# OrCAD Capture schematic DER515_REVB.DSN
size B
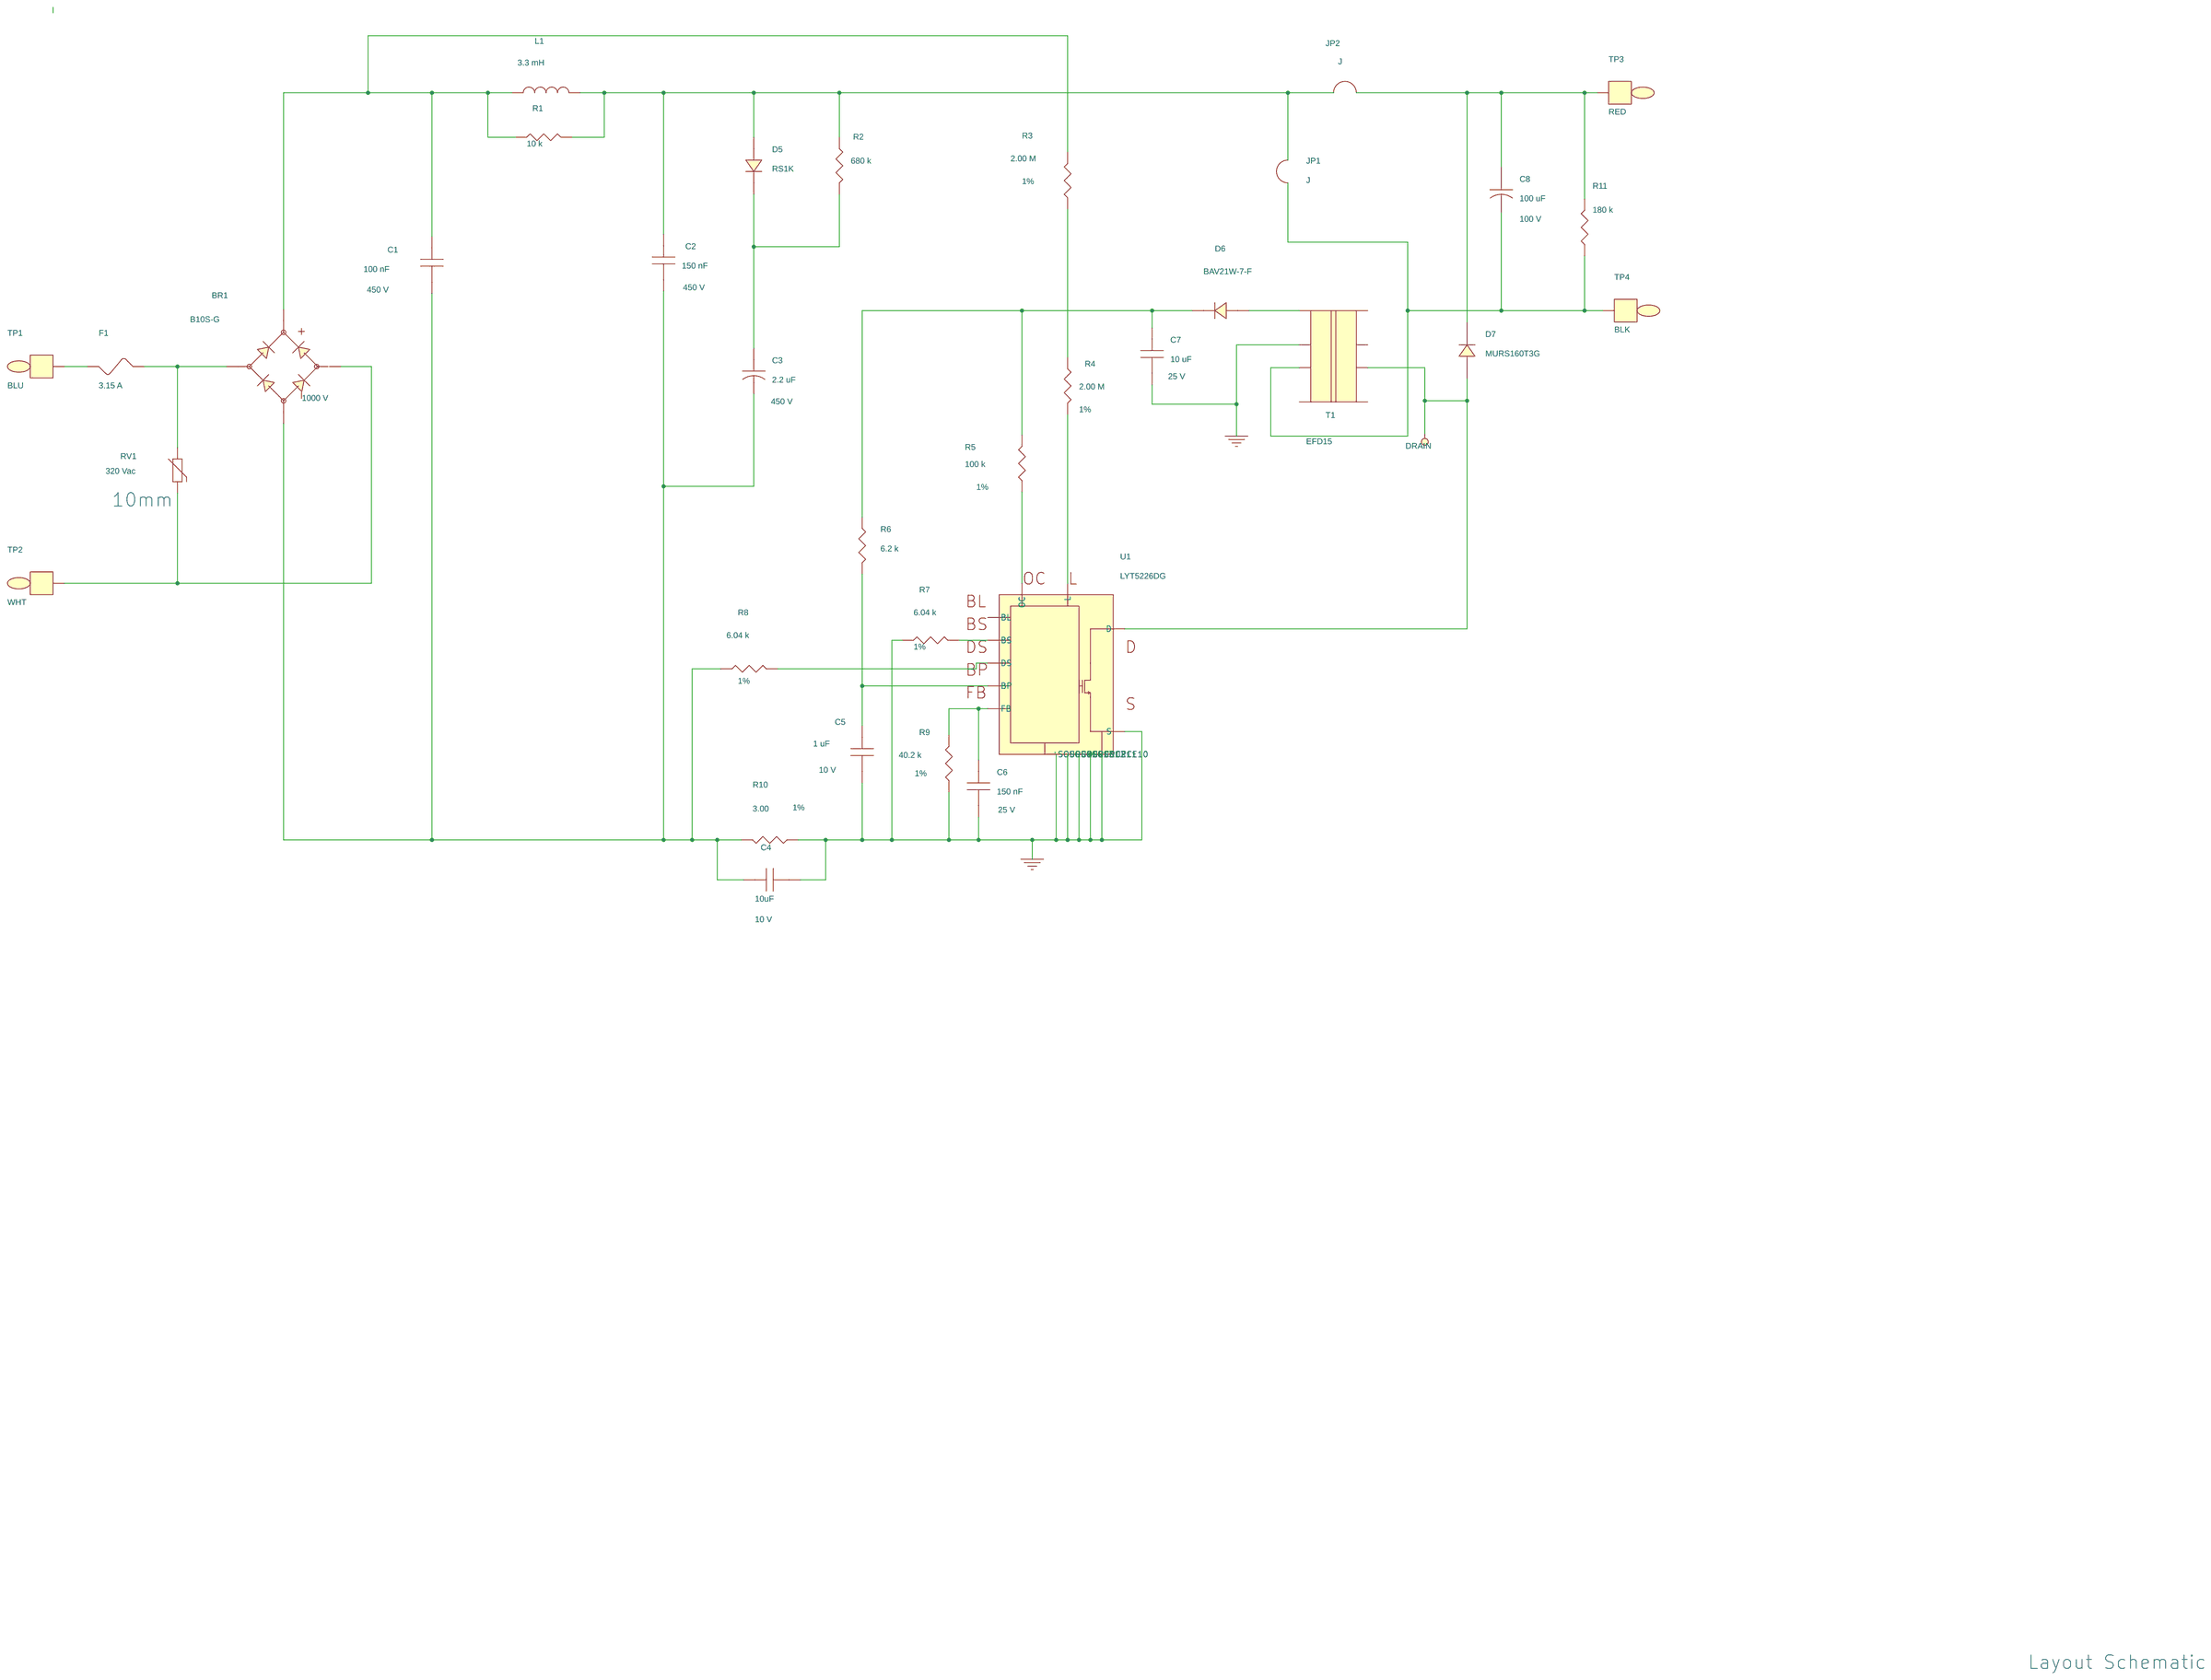
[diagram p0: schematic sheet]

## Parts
BR1  B10S-G  [pismsoic4]
C1  100 nF  [pinpcaprad440x200300040]
C2  150 nF  [pi_np_cap400x240ls300d030]
C3  2.2 uF  [pipolcapclyd320ls140030]
C4  10uF  [pismc1206]
C5  1 uF  [pismc0805]
C6  150 nF  [pismc0805]
C7  10 uF  [pismc1206]
C8  100 uF  [pipolcapcyld400ls200040]
D5  RS1K  [pismdsma]
D6  BAV21W-7-F  [pi_sm_sod-123_12]
D7  MURS160T3G  [pismsmb]
F1  3.15 A  [pi_v_ax_3-6x10_145ls200d030]
JP1  J  [pi_jumper300]
JP2  J  [pi_jumper300]
L1  3.3 mH  [pi_choke_450hx375ls197d030_h]
R1  10 k  [pismr0805]
R2  680 k  [pismr1206]
R3  2.00 M  [pismr1206]
R4  2.00 M  [pismr1206]
R5  100 k  [pismr0805]
R6  6.2 k  [pismr0805]
R7  6.04 k  [pismr0805]
R8  6.04 k  [pismr0805]
R9  40.2 k  [pismr0805]
R10  3.00  [pismr1206]
R11  180 k  [pismr1206]
RV1  320 Vac  [pi_rad450x550ls300d040_h]
T1  EFD15  [pi_bobbin_efd15_8p]
TP1  BLU  [pitpkeystone125x125]
TP2  WHT  [pitpkeystone125x125]
TP3  RED  [pitpkeystone125x125]
TP4  BLK  [pitpkeystone125x125]
U1  LYT5226DG  [pi_smd_so_14-16p_short9-14]

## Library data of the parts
BR1 = DIODE_BRIDGE_~~+-: ALT_SYMBOLS: pi_sm_soic4_slot; Disp_Voltage: 1000 V; FPLIST: pismsoic4,pi_sm_soic4_slot; Part Number: 15-00818-00
C1 = CAP_NP: ALT_SYMBOLS: pinpcaprad440x200300040h; Disp_Voltage: 450 V; FPLIST: pinpcaprad440x200300040,pinpcaprad440x200300040h; Part Number: 20-08690-00; Voltage: 450 V
C2 = CAP_NP: Disp_Voltage: 450 V; Part Number: 20-08937-00; Voltage: 450 V
C3 = CAP_POL: Disp_Voltage: 450 V; Part Number: 20-08936-00; Voltage: 450 V
C4 = CAP_NP: Disp_Voltage: 10 V; Part Number: 20-08935-00; Voltage: 10 V
C5 = CAP_NP: Disp_Voltage: 10 V; Part Number: 20-08934-00; Voltage: 10 V
C6 = CAP_NP: Disp_Voltage: 25 V; Part Number: 20-00236-00; Voltage: 25 V
C7 = CAP_NP: Disp_Voltage: 25 V; Part Number: 20-08608-00; Voltage: 25 V
C8 = CAP_POL: ALT_SYMBOLS: pipolcapcyld400ls200040800h; Disp_Voltage: 100 V; FPLIST: pipolcapcyld400ls200040,pipolcapcyld400ls200040800h; Part Number: 20-01121-00; Voltage: 100 V
D5 = DIODE: Part Number: 15-00433-00
D6 = DIODE: Part Number: 15-00993-00
D7 = DIODE: Part Number: 15-00487-00
F1 = FUSE: FPLIST: pi_v_ax_3-6x10_145ls200d030,pi_axial_3_6x10_145ls500d030; Part Number: 40-00064-00
JP1 JP2 = JUMPER_1: Part Number: 65-00120-00
L1 = INDUCTOR: FPLIST: pi_choke_450hx375ls197d030,pi_choke_450hx375ls197d030_h; Part Number: 30-00328-00
R1 = R: Part Number: 05-01543-00
R2 = R: Part Number: 05-01420-00
R3 R4 = R: Disp_Tol: 1%; Part Number: 05-03156-00
R5 = R: Disp_Tol: 1%; Part Number: 05-00780-00
R6 = R: Part Number: 05-01538-00
R7 R8 = R: Disp_Tol: 1%; Part Number: 05-03381-00
R9 = R: Disp_Tol: 1%; Part Number: 05-00742-00
R10 = R: Disp_Tol: 1%; Part Number: 05-05558-00
R11 = R: Part Number: 05-01406-00
RV1 = VARISTOR: FPLIST: pidisc500x225ls335x140040,pi_rad450x550ls300d040_h; Part Number: 85-00008-00
T1 = BEFD15_8P_GENERIC: ALT_SYMBOLS: pi_bobbin_efd15_8p_tape; FPLIST: pi_bobbin_efd15_8p,pi_bobbin_efd15_8p_tape; Part Number: 25-00036-00
TP1 = TESTPOINT: Part Number: 35-00185-00
TP2 = TESTPOINT: Part Number: 35-00044-00
TP3 = TESTPOINT: Part Number: 35-00043-00
TP4 = TESTPOINT: Part Number: 35-00042-00
U1 = LYTSW-3_SO-16: Part Number: 10-00800-00

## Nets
GND: C4.2 C5.2 C6.2 C7.2 R7.2 R9.1 R10.1 T1.7 U1.9(S) U1.10(SOURCE10) U1.11(SOURCE11) U1.12(SOURCE12) U1.13(SOURCE13) U1.14(SOURCE14)
Drain: D7.2 T1.3 U1.8(D)
N3973903: BR1.2 RV1.2 TP2.1
N3973993: BR1.3 C1.1 L1.1 R1.1 R3.1
N3974125: BR1.4 C1.2 C2.2 C3.2 C4.1 R8.2 R10.2
N3974133: C8.1 D7.1 JP2.2 R11.1 TP3.1
N3974639: C2.1 D5.2 JP1.2 JP2.1 L1.2 R1.2 R2.1
N3976866: F1.2 TP1.1
N3988468: C5.1 R6.2 U1.15(BP)
N3988573: C6.1 R9.2 U1.1(FB)
N3988655: R8.1 U1.4(DS)
N3988764: R7.1 U1.3(BS)
N3989804: C7.1 D6.1 R5.2 R6.1
N4093345: C3.1 D5.1 R2.2
N4093437: BR1.1 F1.1 RV1.1
N4099337: D6.2 T1.8
N4099428: C8.2 JP1.1 R11.2 T1.6 TP4.1
N4143937: R3.2 R4.1
N4145625: R4.2 U1.2(L)
N4148511: R5.1 U1.16(OC)

Not connected (* = marked no-connect by the designer): T1 1 2 4 5; U1 5(BL)

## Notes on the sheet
- 10mm
- Layout Schematic
